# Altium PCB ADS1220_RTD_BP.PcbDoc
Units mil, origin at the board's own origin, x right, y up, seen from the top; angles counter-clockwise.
Board outline 2300 x 1130 mil, 2 copper layers (Top Layer, Bottom Layer), stack 62 mil thick; 26 components, 24 nets, 111 pads, 23 vias.
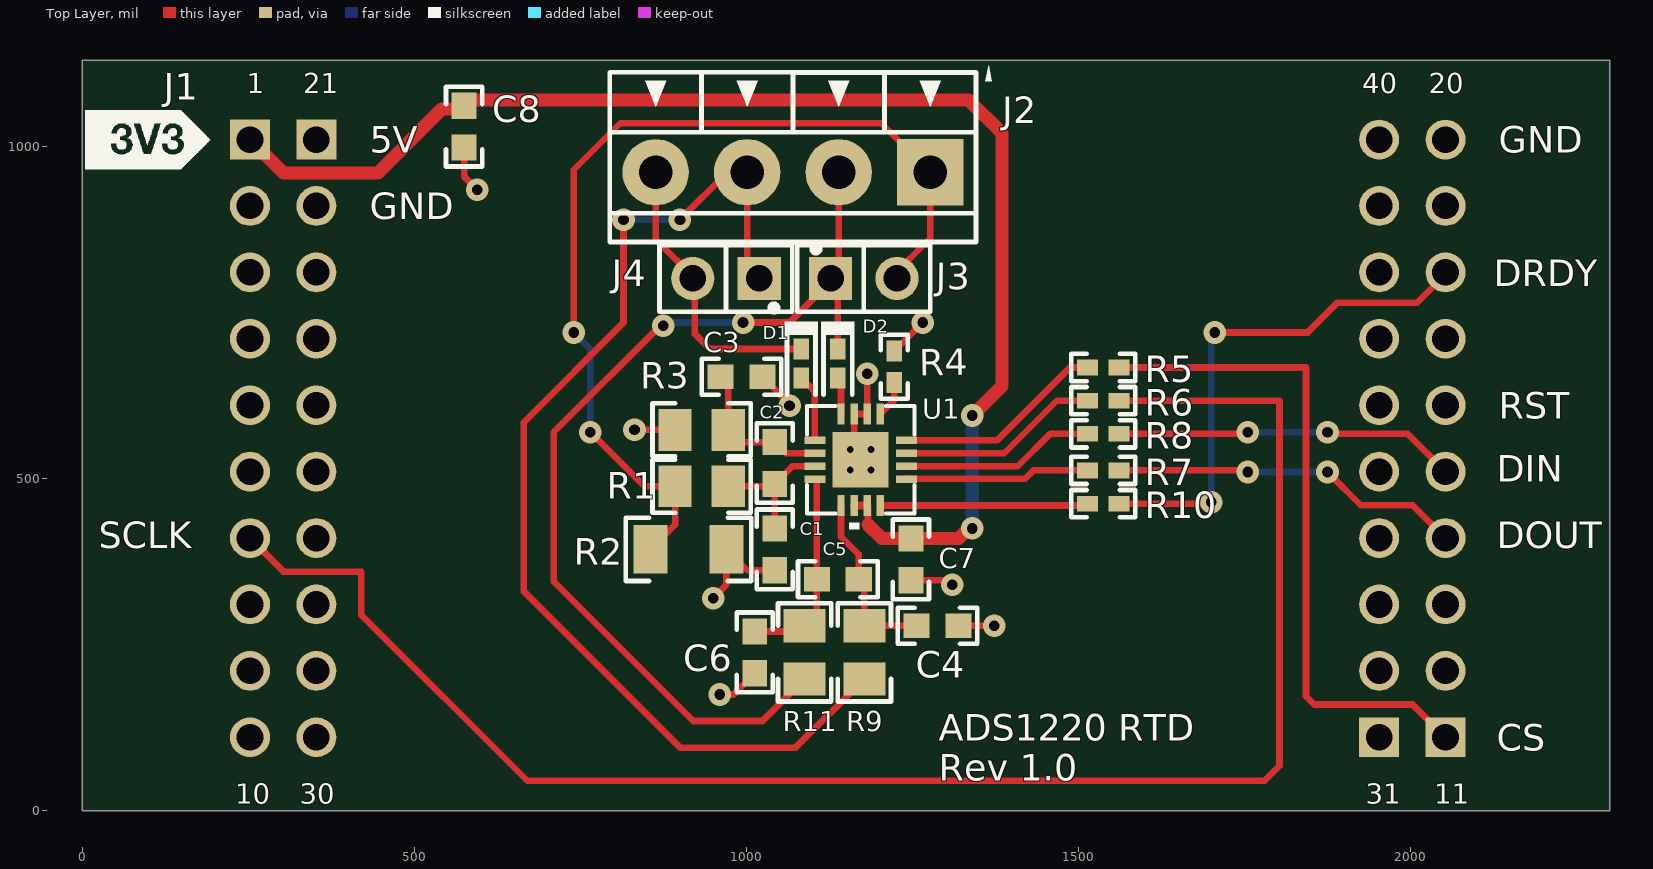
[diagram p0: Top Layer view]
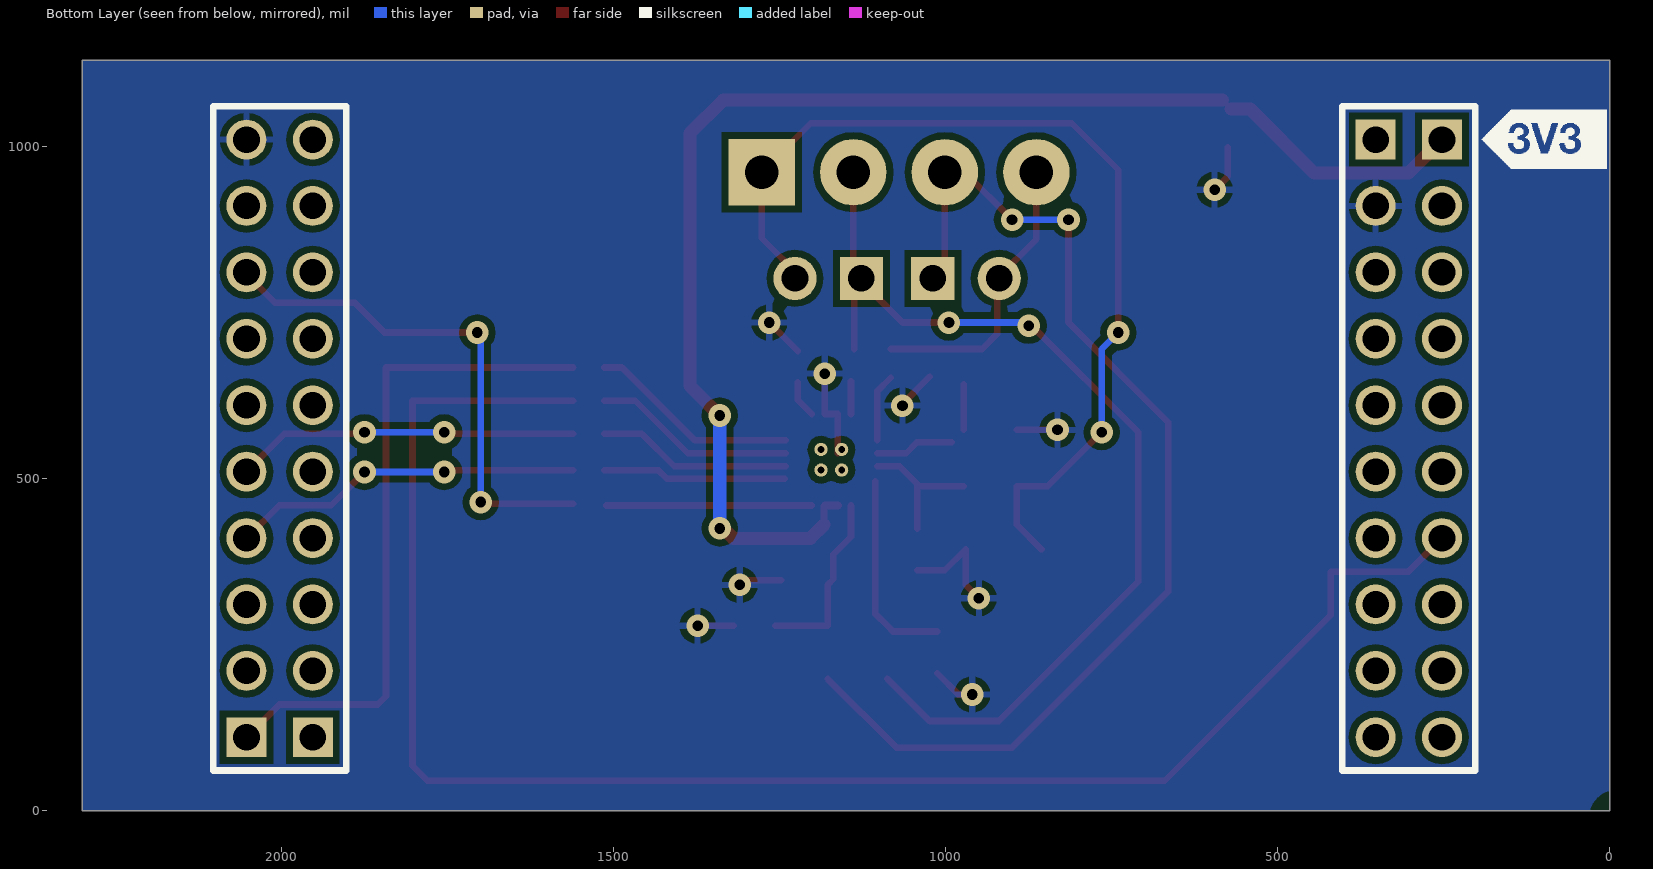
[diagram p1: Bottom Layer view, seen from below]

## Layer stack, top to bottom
Top Solder: solder mask 0.4, Solder Resist, Dk 3.5
Top Layer: signal copper 1.4
Dielectric1: core 59.2, FR-4, Dk 4.8
Bottom Layer: signal copper 1.4
Bottom Solder: solder mask 0.4, Solder Resist, Dk 3.5

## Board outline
0,0 2300,0 2300,1130 0,1130 0,0

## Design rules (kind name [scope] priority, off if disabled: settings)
AcuteAngle [All] p1: minimum=4.50000000000000E+0001 checktracksonly=FALSE
AssemblyTestPointUsage [All] p1: valid=2
Clearance Clearance_BoardEdge_MountingHoles [OnCopper and InComponentClass('Mounting Holes') vs IsKeepOut] p1: gap=40
Clearance Clearance_BoardEdge_Poly [OnCopper and InPoly vs IsKeepOut] p2: gap=25
Clearance Clearance_BoardEdge [OnCopper and Not InComponentClass('Logo') and not InComponentClass('FiducialMark') and not InRegion(1000,500,4000,800) and Not IsKeepout vs IsKeepOut] p3: gap=75
Clearance Clearance_Poly [InPolygon] p4: gap=10
Clearance [All] p5: gap=8
ComponentClearance ComponentClearance_Shunt [InComponentClass('Header') vs InComponentClass('Shunt')] p1: gap=0 collisioncheckmode=3 verticalgap=0 showdistances=FALSE
ComponentClearance ComponentClearance_Logo [InComponentClass('Logo')] p2: gap=0 collisioncheckmode=3 verticalgap=0 showdistances=FALSE
ComponentClearance ComponentClearance_ScrewToNut [(HasFootprint('NY PMS 440 0025 PH')) vs (HasFootprint('Keystone_1902C'))] p3: gap=0 collisioncheckmode=3 verticalgap=0 showdistances=FALSE
ComponentClearance ComponentClearance_MountingHoles [InComponentClass('Mounting Holes')] p4: gap=0 collisioncheckmode=3 verticalgap=100000 showdistances=FALSE
ComponentClearance ComponentClearance_SmallPassives [HasFootprint('0201*') or HasFootprint('0402*') or HasFootprint('0508') or HasFootprint('0603*') or HasFootprint('0612') or HasFootprint('0805*') or HasFootprint('0815*') or HasFootprint('0830*') or HasFootprint('1206*') or HasFootprint('1210*') or HasFootprint('1808*') or HasFootprint('1812*') or HasFootprint('1825*') or HasFootprint('2010*') or HasFootprint('2220*') or HasFootprint('2225*') or HasFootprint('2512*') or HasFootprint('2728*') or HasFootprint('3518*') vs HasFootprint('0201*') or HasFootprint('0402*') or HasFootprint('0508') or HasFootprint('0603*') or HasFootprint('0612') or HasFootprint('0805*') or HasFootprint('0815*') or HasFootprint('0830*') or HasFootprint('1206*') or HasFootprint('1210*') or HasFootprint('1808*') or HasFootprint('1812*') or HasFootprint('1825*') or HasFootprint('2010*') or HasFootprint('2220*') or HasFootprint('2225*') or HasFootprint('2512*') or HasFootprint('2728*') or HasFootprint('3518*')] p5: gap=0 collisioncheckmode=3 verticalgap=0 showdistances=FALSE
ComponentClearance ComponentClearance_THtoSMT [IsThruComponent vs IsSMTComponent] p6: gap=0 collisioncheckmode=3 verticalgap=0 showdistances=FALSE
ComponentClearance ComponentClearance_THtoTH [IsThruComponent vs IsThruComponent] p7: gap=0 collisioncheckmode=3 verticalgap=0 showdistances=FALSE
ComponentClearance [All] p8: gap=0 collisioncheckmode=3 verticalgap=0 showdistances=FALSE
DiffPairsRouting [All] p1: maxlimit=100 minlimit=10 mostfreqgap=10 toplayer_minwidth=15 toplayer_maxwidth=15 toplayer_prefwidth=15 bottomlayer_minwidth=15 bottomlayer_maxwidth=15 bottomlayer_prefwidth=15 maxuncoupledlength=1000
FabricationTestPointUsage TestPointUsage [All] p1: valid=2 allowmultiple=FALSE
FabricationTestpoint Testpoint [All] p1: side=3 testpointundercomponent=TRUE minsize=40 maxsize=100 preferedsize=60 minholesize=0 maxholesize=40 preferedholesize=32 testpointgrid=1 allowsidetop=TRUE allowsidebottom=TRUE usegrid=TRUE gridtolerance=0.01
FanoutControl Fanout_LCC [IsLCC] p1: bgadir=Out bgaviamode=Centered fanoutstyle=Auto fanoutdirection=Alternating viagrid=1 // Fanout_LCC (Default Rule)
FanoutControl Fanout_BGA [IsBGA] p2: bgadir=Out bgaviamode=Centered fanoutstyle=Auto fanoutdirection=Alternating viagrid=1 // Fanout_BGA (Default Rule)
FanoutControl Fanout_Default [All] p4: bgadir=Out bgaviamode=Centered fanoutstyle=Auto fanoutdirection=Alternating viagrid=1 // Fanout_Default (Default Rule)
FanoutControl Fanout_Small [(CompPinCount < 5)] p5: bgadir=Out bgaviamode=Centered fanoutstyle=Auto fanoutdirection=OutThenIn viagrid=1 // Fanout_Small (Default Rule)
HoleSize [All] p1: absolutevalues=TRUE maxlimit=251 minlimit=8 maxpercent=80.000 minpercent=20.000
MinimumAnnularRing MinimumAnnularRing_ThermalPadVias [IsVia and InAnyComponent] p1: minimumring=5.91
MinimumAnnularRing [All] p2: minimumring=9
MinimumSolderMaskSliver MinimumSolderMaskSliver_Logo [InComponentClass('Logo') vs InComponentClass('Logo')] p1: minsoldermaskwidth=0.7
MinimumSolderMaskSliver [All] p2: minsoldermaskwidth=3.94
PlaneConnect [All] p1: planeconnectstyle=Relief reliefexpansion=10 reliefentries=4 reliefconductorwidth=10 reliefairgap=10
PolygonConnect [All] p1: connectstyle=Relief reliefconductorwidth=10 reliefentries=4 polygonreliefangle="90 Angle" airgapwidth=10
RoomDefinition ADS1220_RTD_BP [InComponentClass('ADS1220_RTD_BP')] p1: confinementstyle=ConfineIn formatcopy=TRUE lockcomponents=FALSE outline -692,-1534 1308,-1534 1308,-534 -692,-534
RoutingVias ThermalPadVias [IsVia and InAnyComponent] p1: holewidth=7.87 width=19.68 viastyle="Through Hole" minholewidth=7.87 minwidth=19.68 maxholewidth=12.99 maxwidth=23.62
RoutingVias [All] p2: holewidth=16 width=34 viastyle="Through Hole" minholewidth=7.87 minwidth=26 maxholewidth=40 maxwidth=65
SMDToCorner [All] p1: distance=30000
SilkToSilkClearance [All] p1: silktosilkclearance=5
SilkToSolderMaskClearance SilkscreenOverComponentPads [IsPad] p1: minsilkscreentomaskgap=5 clearancetoexposedcopper=TRUE
SolderMaskExpansion SolderMaskExpansion_via [IsVia] p1: expansion=-17
SolderMaskExpansion [All] p2: expansion=1.97
UnpouredPolygon [All] p1: allowunpoured=FALSE
Width [All] p1: maxlimit=100 minlimit=6 preferedwidth=10 checkconnectedcopper=TRUE
15 further rules are at their usual default settings.

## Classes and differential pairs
component class Header: J3 J4

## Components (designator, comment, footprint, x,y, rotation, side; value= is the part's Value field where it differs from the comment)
C1 "GRM188R72A182KA01D" 0603 1042.65,393.44 r270 top
C2 "C0603C183K1RACTU" 0603 1042.65,523.44 r90 top
C3 "GRM188R72A182KA01D" 0603 992.65,653.44 r180 top
C4 "GRM188R72A272KA01D" 0603 1287.65,278.44 r0 top
C5 "C0603C273K1RACTU" 0603 1137.65,348.44 r180 top
C6 "GRM188R72A272KA01D" 0603 1012.65,238.44 r90 top
C7 "C0603X104K4RACTU" 0603 1247.65,378.44 r270 top
C8 "C0603X104K4RACTU" 0603 575,1030 r270 top
D1 "ZHCS350TA" SOD-523 1082.65,673.44 r270 top
D2 "ZHCS350TA" SOD-523 1137.65,673.44 r270 top
J1 "SSW-110-23-F-D (requires 2)" "40Pin BP" 1152.65,560.53 r0 top
J2 "ED555/4DS" TERM_BLK_ED555-4DS 1276.79,961.38 r180 top
J3 "TSW-102-07-G-S" TSW-102-07-G-S 1176.79,801.38 r0 top
J4 "TSW-102-07-G-S" TSW-102-07-G-S 969.31,801.38 r180 top
R1 "RG2012P-4221-B-T5" 0805_HV 932.65,488.44 r0 top
R2 "PFC-W1206R-12-3241-B" 1206 912.65,393.44 r180 top
R3 "RG2012P-4221-B-T5" 0805_HV 932.65,573.44 r0 top
R4 "CRCW040210K0FKEDHP" 0402 1222.65,668.44 r270 top
R5 "CRCW04020000Z0ED" 0402 1537.39,667.37 r0 top
R6 "CRCW04020000Z0ED" 0402 1537.39,617.37 r0 top
R7 "CRCW04020000Z0ED" 0402 1537.39,512.37 r180 top
R8 "CRCW04020000Z0ED" 0402 1537.39,567.37 r0 top
R9 "RG2012P-4221-B-T5" 0805_HV 1177.65,238.44 r90 top
R10 "CRCW04020000Z0ED" 0402 1537.39,462.37 r180 top
R11 "RG2012P-4221-B-T5" 0805_HV 1087.65,238.44 r90 top
U1 "ADS1220_RVA_16" RVA16_2P14X2P14 1172.09,528.44 r270 top

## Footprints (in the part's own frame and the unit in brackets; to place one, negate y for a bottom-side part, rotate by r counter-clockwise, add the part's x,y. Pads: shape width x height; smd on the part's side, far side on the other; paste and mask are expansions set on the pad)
"40Pin BP" [mil] "40Pin Booster Pack Connection (Top - male; Bottom - female)"
  rect 60x60 hole 40: 1(-900,450) 11(900,-450) 21(-800,450) 31(800,-450)
  round 60 hole 40: 2(-900,350) 3(-900,250) 4(-900,150) 5(-900,50) 6(-900,-50) 7(-900,-150) 8(-900,-250) 9(-900,-350) 10(-900,-450) 12(900,-350) 13(900,-250) 14(900,-150) 15(900,-50) 16(900,50) 17(900,150) 18(900,250) 19(900,350) 20(900,450) 22(-800,350) 23(-800,250) 24(-800,150) 25(-800,50) 26(-800,-50) 27(-800,-150) 28(-800,-250) 29(-800,-350) 30(-800,-450) 32(800,-350) 33(800,-250) 34(800,-150) 35(800,-50) 36(800,50) 37(800,150) 38(800,250) 39(800,350) 40(800,450)
  silkscreen extent -1148,406 -960,494, body extent -950,-500 950,500, height 335
0402 [mm] "0402 from SM-752 data"
  rect 0.8x0.6 smd: 1(-0.6,0) 2(0.6,0)
  silkscreen extent -1.22,-0.52 1.22,0.52, body extent -0.55,-0.3 0.55,0.3, height 0.6
0603 [mm] "0603 from SM-752 data"
  rect 1x0.95 smd: 1(-0.8,0) 2(0.8,0)
  silkscreen extent -1.52,-0.69 1.52,0.69, body extent -0.87,-0.47 0.87,0.47, height 0.85
0805_HV [mil] "0805 with 30mil clearance between pads"
  rect 50x63 smd: 1(-40,0) 2(40,0)
  silkscreen extent -74,-40 74,40, body extent -43,-29 43,29, height 43
1206 [mm] "1206 from SM-752 data"
  rect 1.3x1.85 smd: 1(-1.45,0) 2(1.45,0)
  silkscreen extent -2.4,-1.21 2.4,1.21, body extent -1.7,-0.9 1.7,0.9, height 1.35
RVA16_2P14X2P14 [mm]
  rect 0.8x0.28 smd paste-0.14: 1(-1.75,0.75) 2(-1.75,0.25) 3(-1.75,-0.25) 4(-1.75,-0.75) 9(1.75,-0.75) 10(1.75,-0.25) 11(1.75,0.25) 12(1.75,0.75)
  rect 0.28x0.8 smd paste-0.14: 5(-0.75,-1.75) 6(-0.25,-1.75) 7(0.25,-1.75) 8(0.75,-1.75) 13(0.75,1.75) 14(0.25,1.75) 15(-0.25,1.75) 16(-0.75,1.75)
  rect 2.14x2.14 smd paste-1.057 mask-1.054: 17(0,0)
  round 0.508 / inner round 1.524 / far side round 0.508 hole 0.254: V(-0.394,0.394) V(-0.394,-0.394) V(0.394,0.394) V(0.394,-0.394)
  silkscreen extent -2.06,-2.06 2.66,2.06
SOD-523 [mm] "NXP Semiconductor recommended land pattern, nominal STEP model"
  rect 0.8x0.6 smd paste-0.05: 1(-0.55,0) 2(0.55,0)
  silkscreen extent -1.6,-0.63 1.2,0.64, body extent -0.8,-0.4 0.8,0.4, height 0.72
TERM_BLK_ED555-4DS [mm]
  rect 2.54x2.54 hole 1.27: 1(0,0)
  round 2.54 hole 1.27: 2(3.5,0) 3(7,0) 4(10.5,0)
  silkscreen extent -2.36,-4.09 12.25,2.67, body extent -1.75,-3.8 12.25,2.7, height 8.2
TSW-102-07-G-S [mm] "Samtec 100mil, 1x2, 230 mil above insulator"
  rect 1.65x1.65 hole 1.016 mask+0: 1(-1.27,0)
  round 1.65 hole 1.016 mask+0: 2(1.27,0)
  silkscreen extent -3.56,-1.27 2.54,1.27, body extent -2.54,-1.27 2.54,1.27, height 8.38

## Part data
C1 C3: "CAP, CERM, 1800pF, 100V, +/-10%, X7R, 0603"
C2: "CAP, CERM, 0.018uF, 100V, +/-10%, X7R, 0603"
C4 C6: "CAP, CERM, 2700pF, 100V, +/-10%, X7R, 0603"
C5: "CAP, CERM, 0.027uF, 100V, +/-10%, X7R, 0603"
C7 C8: "CAP, CERM, 0.1uF, 16V, +/-10%, X7R, 0603"
D1 D2: "Diode, Schottky, 40V, 0.35A, SOD-523"
J1: library part "40Pin Booster Pack Connection", "40Pin Booster Pack Connection"
J2: "Terminal Block, 6A, 3.5mm Pitch, 4-Pos, TH"
J3 J4: "Header, 100mil, 2x1, Gold, TH"
R1 R3 R9 R11: "RES, 4.22k ohm, 0.1%, 0.125W, 0805"
R2: "RES, 3.24k ohm, 0.1%, 0.333W, 1206"
R4: library part Resistor, "RES, xxx ohm, x%, xW, [PackageReference]"
R5 R6 R7 R8 R10: "RES, 0 ohm, 5%, 0.063W, 0402"
U1: "Imported"

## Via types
v1: diameter 34, hole 16, Top Layer to Bottom Layer, 23 vias

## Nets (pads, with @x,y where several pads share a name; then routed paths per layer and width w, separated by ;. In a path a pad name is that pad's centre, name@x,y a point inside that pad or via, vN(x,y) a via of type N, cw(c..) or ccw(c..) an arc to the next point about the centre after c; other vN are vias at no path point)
+3V3: C7.1 C8.1 J1.1 U1.10 U1.11 | length 2041.9
  Top Layer w10: U1.11 1183.11,458.37 1183.11,430.79 ; v1(1340,425) v1@1340,430
  Top Layer w12: U1.10 U1.11
  Top Layer w20: J1.1 303.18,960 445,960 541.5,1056.5 C8.1@570,1056.5 ; C8.1@583.5,1070 1295,1070 1335,1070 1385,1020 1385,640 v1(1340,595) ; 1183.11,430.79 1203.96,409.93 C7.1 1319.93,409.93 v1@1340,430
  Bottom Layer w20: v1(1340,425) v1(1340,595)
+5V: J1.21
ADS_CS: J1.11 R5.2 | length 1012.3
  Top Layer w10: R5.2 1842.63,667.37 1842.63,172.37 1855,160 2003.18,160 J1.11
ADS_DRDY: J1.18 R10.1 | length 781.3
  Top Layer w10: R10.1 1697.63,462.37 v1(1700,464.74) ; v1(1705,720) 1845,720 1890,765 2010,765 J1.18@2052.65,807.65
  Bottom Layer w10: v1(1700,464.74) 1700,715 v1(1705,720)
ADS_REFN0: C2.2 C3.2 R3.2 U1.6 | length 187.4
  Top Layer w10: R3.2 C3.2@972.65,641.94 ; R3.2@991.16,554.93 C2.2 1059.3,538.28 U1.6
ADS_REFP0: C1.1 C2.1 R1.2 U1.7 | length 210
  Top Layer w10: R1.2 1039.15,488.44 C2.1 ; C1.1 C2.1 ; U1.7 1069.3,518.59 C2.1
GND: C1.2 C3.1 C4.2 C6.1 C7.2 C8.2 J1.20 J1.22 R2.1 R3.1 R4.1 U1.2 U1.3 U1.17 | length 746.4
  Top Layer w10: C8.2 575,955 v1(595,935) ; v1(831.56,573.44) R3.1 ; v1(950,320) 969.74,339.74 R2.1 1001.24,361.94 C1.2 ; v1(960,175) 980.71,175 C6.1 ; C3.1 1065,612.59 v1(1065,610) ; U1.17@1162.25,538.28 U1.3 U1.2 v1(1181.93,658.07) ; R4.1 v1(1265.59,735) ; C7.2 1303.06,346.94 v1(1310,340) ; C4.2 v1(1373.44,278.44)
NetC4_1: C4.1 C5.1 R9.2 U1.9 | length 274.1
  Top Layer w10: U1.9 1142.56,412.44 1169.15,385.85 C5.1 1177.65,339.93 R9.2 C4.1
NetC5_2: C5.2 C6.2 R11.2 U1.8 | length 303.7
  Top Layer w10: C6.2 1079.15,269.93 R11.2 1106.16,296.94 C5.2 U1.8@1106.16,495.94
NetD1_1: D1.1 J2.4 J4.2 | length 437.8
  Top Layer w10: J2.4 863.4,860.4 922.42,801.38 922.42,717.58 944.91,695.09 D1.1
NetD1_2: D1.2 U1.5 | length 102.3
  Top Layer w10: D1.2 1103.19,631.24 U1.5
NetD2_1: D2.1 J2.2 J3.1 R11.1 | length 1500.3
  Top Layer w10: v1(875,730) 870,730 710,570 710,345 920,135 1024.22,135 R11.1 ; v1(995,735) 1065,735 J3.1@1132.96,802.96 ; D2.1 J3.1@1137.65,801.62 ; J3.1@1138.99,802.96 J2.2
  Bottom Layer w10: v1(875,730) 880,735 v1(995,735)
NetD2_2: D2.2 U1.4 | length 49.5
  Top Layer w10: U1.4 D2.2@1142.56,646.87
NetJ2_1: J2.1 J3.2 R1.1 R2.2 | length 1458.5
  Top Layer w10: v1(740,720) 740,965 810,1035 1203.17,1035 J2.1 1276.79,862.01 J3.2@1216.16,801.38 ; v1(765,570) 846.56,488.44 R1.1 892.65,430.52 R2.2
  Bottom Layer w10: v1(740,720) 765,695 v1(765,570)
NetJ2_3: J2.3 J4.1 R9.1 | length 1650.7
  Top Layer w10: v1(815,890) 815,735 665,585 665,330 900,95 1074.22,95 R9.1 ; v1(900,890) 971.38,961.38 J2.3 J4.1@1001.2,801.42
  Bottom Layer w10: v1(815,890) v1(900,890)
NetR4_2: R4.2 U1.1 | length 56.2
  Top Layer w10: U1.1 1222.65,618.37 R4.2
NetR5_1: R5.1 U1.16 | length 318.1
  Top Layer w10: U1.16 1377.97,557.97 1487.37,667.37 R5.1
NetR6_1: R6.1 U1.15 | length 305.5
  Top Layer w10: U1.15 1388.28,538.28 1467.37,617.37 R6.1
NetR7_2: R7.2 U1.13 | length 276.8
  Top Layer w10: U1.13@1242.09,500 1420,500 1432.37,512.37 R7.2
NetR8_1: R8.1 U1.14 | length 293
  Top Layer w10: U1.14 1408.59,518.59 1457.37,567.37 R8.1
NetR10_2: R10.2 U1.12 | length 309.3
  Top Layer w10: U1.12 R10.2@1510.94,459.54
SPI_CLK: J1.7 R6.2 | length 2540.2
  Top Layer w10: J1.7 303.18,360 420,360 420,295 670,45 1780,45 1802.63,67.63 1802.63,617.37 R6.2
SPI_MISO: J1.14 R7.1 | length 533.8
  Top Layer w10: R7.1 1752.63,512.37 v1(1755,510) ; v1(1875,510) 1925,460 2003.18,460 J1.14
  Bottom Layer w10: v1(1755,510) v1(1875,510)
SPI_MOSI: J1.15 R8.2 | length 517.4
  Top Layer w10: R8.2 1752.63,567.37 v1(1755,569.74) ; v1(1875,570) 1877.47,567.53 1995.65,567.53 J1.15
  Bottom Layer w10: v1(1755,569.74) 1874.74,569.74 v1(1875,570)
pads on no net: J1.2 J1.3 J1.4 J1.5 J1.6 J1.8 J1.9 J1.10 J1.12 J1.13 J1.16 J1.17 J1.19 J1.23 J1.24 J1.25 J1.26 J1.27 J1.28 J1.29 J1.30 J1.31 J1.32 J1.33 J1.34 J1.35 J1.36 J1.37 J1.38 J1.39 J1.40 U1.V

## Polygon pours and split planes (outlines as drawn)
GND on Bottom Layer "BOT_GND" (solid, remove dead copper, pour order 2): 0,0 2300,0 2300,1130 0,1130 0,0

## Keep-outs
Keep-Out Layer:
  text ".Layer_Name" at 577,-858.49 h60

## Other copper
Top Layer:
  text ".Layer_Name" at 577,-858.49 h60
Bottom Layer:
  text ".Layer_Name" at 577,-858.49 h60

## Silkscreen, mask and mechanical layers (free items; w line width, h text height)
Top Overlay:
  text "DRDY" at 2125,790 h40
  text "DIN" at 2130,495 h40
  text "SCLK" at 25,395 h40
  text "DOUT" at 2130,395 h40
  text "ADS1220 RTD" at 1290,105 h40
  text "CS" at 2130,90 h40
  text "Rev 1.0" at 1290,45 h40
  text ".Layer_Name" at 577,-858.49 h60
Bottom Overlay:
  text ".Layer_Name" at 577,-858.49 h60
Top Paste:
  text ".Layer_Name" at 577,-858.49 h60
Bottom Paste:
  text ".Layer_Name" at 577,-858.49 h60
Top Solder:
  text ".Layer_Name" at 577,-858.49 h60
  text ".Layer_Name" at 577,-858.49 h60
Bottom Solder:
  text ".Layer_Name" at 577,-858.49 h60
Drill Guide:
  text ".Layer_Name" at 577,-858.49 h60
M1 Board Outline:
  the board outline again, w10
  text ".Layer_Name" at 577,-858.49 h60
M2 Board Dimensions:
  rectangle: 124.5,-410.5 499.5,-285.5
  rectangle: -0.5,-285.5 124.5,-160.5
  lines w7: -0.5,-285.5 999.5,-285.5 ; 124.5,-410.5 124.5,-160.5 ; 249.5,-410.5 249.5,-160.5 ; 499.5,-410.5 499.5,-160.5 ; 749.5,-410.5 749.5,-160.5 ; -0.5,-410.5 -0.5,-160.5 999.5,-160.5 999.5,-410.5 -0.5,-410.5
  lines w10: -0.5,-475.5 -0.5,-455.5 ; 59.5,-485.5 -0.5,-465.5 ; 59.5,-445.5 -0.5,-465.5 ; 223.58,-465.5 -0.5,-465.5 ; 775.42,-465.5 999.5,-465.5 ; 939.5,-485.5 999.5,-465.5 ; 939.5,-445.5 999.5,-465.5 ; 999.5,-475.5 999.5,-455.5
  text "1000 (mil)" at 233.58,-501.49 h60
  text ".Layer_Name" at 577,-858.49 h60
M3 3D STEP Top:
  text ".Layer_Name" at 577,-858.49 h60
M4 3D STEP Bottom:
  text ".Layer_Name" at 577,-858.49 h60
M5 Assembly Top:
  lines w10: -292,-930.17 6308,-930.17 ; -292,-726.83 6310,-726.83 ; -292,-523.5 -292,-1133.5 3713,-1133.5 6310,-1133.5 6310,-523.5 -291.5,-523.5 -291.5,-1133.5 1284,-1133.5 ; 2173,-1133.5 2173,-523.5 ; 3440,-726.83 3440,-523.5 ; 4280,-726.83 4280,-523.5 ; 4902,-1140 4902,-937.17
  text "COMPONENTS MARKED 'DNP' SHOULD NOT BE POPULATED." at 1153.5,-318.5 h60
  text "ASSEMBLY VARIANT:" at 1153,-434 h60
  text ".VariantName" at 2189,-434 h60
  text "PCB VIEWED FROM TOP SIDE" at -228.5,-655.67 h60
  text "BOARD #:" at 2248,-655.67 h60
  text ".PRJ_Number" at 2793.5,-655.67 h60
  text "REV:" at 3638,-655.67 h60
  text ".PCB_Rev" at 3929.5,-655.67 h60
  text "SVN REV:" at 4476,-655.67 h60
  text ".VersionControl_RevNumber" at 4982,-655.67 h60
  text "IGNORE ->" at -228.5,-858.49 h60
  text "PLOT NAME =" at -228.5,-1064.34 h60
  text ".plot_File_Name" at 577,-1064.34 h60
  text "GENERATED    :" at 2250,-1064.34 h60
  text ".Print_Date" at 3119.5,-1064.34 h60
  text ".Print_Time" at 3848.5,-1064.34 h60
  text "TEXAS INSTRUMENTS" at 5113,-1064.34 h60
M6 Assembly Bottom:
  lines w10: -292.5,-727.33 6309.5,-727.33 ; -290.5,-930.67 6309.5,-930.67 ; 1115.5,-1140.5 1115.5,-937.67 ; 1737.5,-727.33 1737.5,-524 ; 2577.5,-727.33 2577.5,-524 ; 3844.5,-1134 3844.5,-524 ; 4733.5,-1134 6309,-1134 6309,-524 -292.5,-524 -292.5,-1134 2304.5,-1134 6309.5,-1134 6309.5,-524
  text "COMPONENTS MARKED 'DNP' SHOULD NOT BE POPULATED." at 6102,-318 h60
  text ".VariantName" at 5058,-434 h60
  text "ASSEMBLY VARIANT:" at 6097,-434 h60
  text ".VersionControl_RevNumber" at 1035.5,-656.17 h60
  text "SVN REV:" at 1541.5,-656.17 h60
  text ".PCB_Rev" at 2088,-656.17 h60
  text "REV:" at 2379.5,-656.17 h60
  text ".PRJ_Number" at 3224,-656.17 h60
  text "BOARD #:" at 3769.5,-656.17 h60
  text "PCB VIEWED FROM BOTTOM SIDE" at 6246,-656.17 h60
  text "IGNORE ->" at 2547.85,-858.49 h60
  text "TEXAS INSTRUMENTS" at 904.5,-1064.84 h60
  text ".Print_Time" at 2169,-1064.84 h60
  text ".Print_Date" at 2898,-1064.84 h60
  text "GENERATED    :" at 3767.5,-1064.84 h60
  text ".plot_File_Name" at 5440.5,-1064.84 h60
  text "PLOT NAME =" at 6246,-1064.84 h60
M9 Title Sheet:
  drawing of 57 lines, arcs and shapes, not listed
  text "1" at 739.84,8036.5 h70
  text "2" at 3235.5,8036.5 h70
  text "3" at 5724.84,8036.5 h70
  text "4" at 8231.51,8036.5 h70
  text "5" at 10730.5,8036.5 h70
  text "6" at 13235.5,8036.5 h70
  text "A" at -416.5,6893.5 h70
  text "A" at 14383.5,6893.5 h70
  text "B" at -416.5,4513.5 h70
  text "B" at 14383.5,4513.5 h70
  text "C" at -416.5,2138.5 h70
  text "C" at 14383.5,2138.5 h70
  text "PROJECT TITLE:" at 11343.5,277.5 h45
  text ".PRJ_Title" at 11393.5,144.17 h70
  text "DESIGNED FOR:" at 11343.5,-23.5 h45
  text ".PRJ_Customer" at 11393.5,-163.5 h70
  text "D" at -416.5,-231.5 h70
  text "D" at 14383.5,-231.5 h70
  text "FILE NAME:" at 11343.5,-323.5 h45
  text ".PCB_File_Name_No_Path" at 11393.5,-443.5 h70
  text "Texas Instruments (TI) and/or its licensors do not warrant the accuracy or completeness of this specification" at 6374,-605.34 h45
  text "ENGINEER:" at 11343.5,-613.5 h45
  text "LAYOUT BY:" at 12848.5,-613.5 h45
  text "or any information contained therein. TI and/or its licensors do not warrant that this design will meet" at 6329.01,-718 h45
  text ".PRJ_Engineer" at 11393.5,-768.49 h70
  text ".PCB_Layout" at 12899,-768.49 h70
  text "the specifications, will be suitable for your application or fit for any particular purpose, or will operate in" at 6329.01,-830.67 h45
  text ".Layer_Name" at 577,-858.49 h60
  text "ALTIUM DESIGNER VERSION:" at 12848.5,-923.5 h45
  text "an implementation. TI and/or its licensors do not warrant that the design is production worthy. You should" at 6329.01,-943.33 h45
  text "completely validate and test your design implementation to confirm the system functionality for your application." at 6374,-1056 h45
  text ".print_Scale" at 11393.5,-1056.83 h70
  text ".Application_BuildNumber" at 12899,-1056.83 h70
  text "1" at 739.84,-1263.5 h70
  text "2" at 3235.5,-1263.5 h70
  text "3" at 5724.84,-1263.5 h70
  text "4" at 8231.51,-1263.5 h70
  text "5" at 10730.5,-1263.5 h70
  text "6" at 13235.5,-1263.5 h70
M10 Fab Notes:
  drawing of 212 lines, arcs and shapes, not listed
  text "DESIGN INFORMATION" at 12381.02,6810 h60
  text "(REFER ALSO ARRAY/PANEL PROFILING INFORMATION)" at 12019.46,6648.29 h60
  text "BOARD SIZE" at 11333.46,6644 h60
  text "3450MIL" at 11795.78,6516.18 h60
  text "X" at 12301.46,6516.18 h60
  text "4950MIL" at 12532.78,6516.18 h60
  text "Number of Layers :" at 11736.46,6319 h60
  text "2" at 12831.27,6309 h60
  text "MIN. TRACK WIDTH:" at 11736.46,6180 h60
  text "8" at 12832.7,6180 h60
  text "MIL" at 12987.46,6180 h60
  text "MIN. CLEARANCE:" at 11736.46,6048 h60
  text "8" at 12832.7,6048 h60
  text "MIL" at 12987.46,6048 h60
  text "MIN. VIA PAD SIZE:" at 11736.46,5916 h60
  text "24" at 12802.71,5916 h60
  text "MIL" at 12987.46,5916 h60
  text "0.05mm (2MIL)" at 12431.46,5774.29 h60
  text "MINIMUM ANNULAR RING" at 11407.23,5770 h60
  text "EXTERNAL" at 13139.46,5770 h60
  text "PER" at 11607.23,5652 h60
  text "IPC-D-275 CLASS 2 LEVEL C" at 11827.23,5652 h60
  text "MIL, HOLES" at 13315.46,5539.71 h60
  text "+/-" at 12923,5539 h60
  text "+/-" at 13777,5539 h60
  text "REGISTRATION TOLERANCES:" at 11407.23,5534 h60
  text "METAL" at 12607,5534 h60
  text "5" at 13183.2,5534 h60
  text "3" at 14016.2,5534 h60
  text "MIL" at 14132.46,5534 h60
  text "MATERIAL:" at 11332.46,5324.54 h60
  text "FR-4 High Tg" at 12318.9,5184.21 h60
  text "FR-408" at 11753.46,5175.64 h60
  text "X" at 12165.46,5175.64 h60
  text "OTHER" at 13241.46,5175.64 h60
  text "62 MIL (1.6mm) +/-10%" at 12073.56,5012.92 h60
  text "THICKNESS:" at 11407.23,5008.64 h60
  text "X" at 11945.4,5008.64 h60
  text "OTHER" at 13358.46,5008.64 h60
  text "TOLERANCE:" at 11407.23,4850.64 h60
  text "X" at 12246.53,4850.64 h60
  text "ANSI IPC-6012 TYPE 3 CLASS 2" at 12433.48,4850.64 h60
  text "OTHER +/-" at 12433.46,4694.64 h60
  text "BOW & TWIST:" at 11407.23,4537.64 h60
  text "X" at 12246.53,4537.64 h60
  text "ANSI IPC-6012 TYPE 3 CLASS 2" at 12433.48,4537.64 h60
  text "OTHER +/-" at 12433.46,4379.13 h60
  text "COPPER THICKNESS (FINISHED):" at 11332.46,4243.64 h60
  text "1.4MIL (1oz)" at 12212.46,4090.92 h60
  text "2MIL (1.4oz)" at 12979.46,4090.92 h60
  text "2.8MIL (2oz)" at 13706.46,4090.92 h60
  text "OUTER:" at 11689.46,4086.64 h60
  text "X" at 12084,4086 h60
  text "1.4MIL (1oz)" at 12212.46,3933.92 h60
  text "2.8MIL (2oz)" at 12979.46,3933.92 h60
  text "N/A" at 13706,3934.29 h60
  text "INNER SIGNAL:" at 11400.38,3929.64 h60
  text "X" at 12085.42,3929.64 h60
  text "DRILLING:" at 11332.46,3790.64 h60
  text "REFERENCE:" at 11407.23,3673.64 h60
  text "X" at 12055.46,3673.64 h60
  text "AS SHOWN" at 12242.46,3673.64 h60
  text "X" at 12956.46,3673.64 h60
  text "NC_DRILL FILES" at 13093.46,3673.64 h60
  text "PTH MIN COPPER THICKNESS:" at 11407.23,3515.64 h60
  text "X" at 12757.46,3515.64 h60
  text "1MIL" at 12894.46,3515.64 h60
  text "OTHER" at 13391.46,3515.64 h60
  text "BOARD FINISH:" at 11332.46,3356.64 h60
  text "SILKSCREEN:" at 11487.68,3238.64 h60
  text "X" at 12436.46,3238.64 h60
  text "TOP" at 12562.46,3238.64 h60
  text "X" at 12946.46,3238.64 h60
  text "BOTTOM" at 13073.46,3238.64 h60
  text "SILKSCREEN COLOR:" at 11487.68,3071.64 h60
  text "X" at 12435.42,3071.64 h60
  text "WHITE" at 12562.46,3071.64 h60
  text "OTHER" at 13073.46,3071.64 h60
  text "SOLDER RESIST COLOR:" at 11487.68,2901.64 h60
  text "X" at 12055.42,2742.44 h60
  text "GREEN" at 12182.46,2742.44 h60
  text "BLUE" at 12773.46,2742.44 h60
  text "OTHER" at 13311.46,2742.44 h60
  text "IMMERSION GOLD (ENIG)" at 12393.46,2553.92 h60
  text "ENEPIG" at 13731,2550.64 h60
  text "SURFACE FINISH:" at 11332.46,2549.64 h60
  text "X" at 12206.51,2549.64 h60
  text "IMM. TIN/SILVER OR EQUIV" at 11662,2392.64 h60
  text "OTHER" at 13093.46,2392.64 h60
  text "ARRAY/PANEL:" at 11332.46,2213.64 h60
  text "CUT AND TRIM PER MECH LAYER 1" at 12393.46,2209.35 h60
  text "N.C. ROUTE" at 12393.46,2057.64 h60
  text "X" at 13072.46,2057.64 h60
  text "V. SCORE" at 13259.46,2057.64 h60
  text "CERTIFICATION:" at 11332.46,1920.64 h60
  text "MATERIALS AND WORKMANSHIP FOR ALL PCBS" at 12057.46,1920.64 h60
  text "TO MEET OR EXCEED THE REQUIREMENTS OF:" at 12057.46,1822.64 h60
  text "X" at 11683.96,1686.13 h60
  text "ANSI IPC-A-600F CLASS ->" at 11822.96,1686.13 h60
  text "X" at 13462.02,1686.13 h60
  text "2" at 13580.96,1686.14 h60
  text "1" at 13265.96,1684.64 h60
  text "3" at 13934.96,1684.64 h60
  text "X" at 11686.02,1526.64 h60
  text "UL 94V-0" at 11822.96,1526.64 h60
  text "X" at 12498.02,1526.64 h60
  text "RoHS" at 12634.96,1526.64 h60
  text "OTHER" at 13279.36,1526.64 h60
  text "PER ORDER" at 13676.42,1526.64 h60
  text "ADDITIONAL REQUIREMENTS:" at 11332.46,1385.64 h60
  text "MICROSECTION:" at 11407.23,1270.64 h60
  text "YES" at 12312.96,1270.64 h60
  text "REQUIRED" at 13174.46,1114.49 h60
  text "BARE BOARD ELEC. TEST:" at 11407.23,1111.64 h60
  text "NONE" at 12712.96,1111.64 h60
  text "X" at 13047.46,1111.64 h60
  text "PER ORDER" at 13766.46,1111.64 h60
  text "MANUFACTURER'S UL:" at 11407.23,954.64 h60
  text "RAIL" at 12572.96,950.35 h60
  text "METAL" at 13064.77,950.35 h60
  text "X" at 13440,950 h60
  text "SILK" at 13576.46,950.35 h60
  text ".Layer_Name" at 577,-858.49 h60
M11 Gerber Information:
  lines w10: -292,-930.17 6308,-930.17 ; -292,-726.83 6310,-726.83 ; -292,-523.5 -292,-1133.5 3713,-1133.5 6310,-1133.5 6310,-523.5 -291.5,-523.5 -291.5,-1133.5 1284,-1133.5 ; 2173,-1133.5 2173,-523.5 ; 3440,-726.83 3440,-523.5 ; 4280,-726.83 4280,-523.5 ; 4902,-1140 4902,-937.17
  text "ALL ARTWORK VIEWED FROM TOP SIDE" at -228.5,-655.67 h60
  text "BOARD #:" at 2248,-655.67 h60
  text ".PRJ_Number" at 2793.5,-655.67 h60
  text "REV:" at 3638,-655.67 h60
  text ".PCB_Rev" at 3929.5,-655.67 h60
  text "SVN REV:" at 4476,-655.67 h60
  text ".VersionControl_RevNumber" at 4982,-655.67 h60
  text "LAYER NAME =" at -228.5,-858.49 h60
  text "PLOT NAME =" at -228.5,-1064.34 h60
  text ".plot_File_Name" at 577,-1064.34 h60
  text "GENERATED    :" at 2250,-1064.34 h60
  text ".Print_Date" at 3119.5,-1064.34 h60
  text ".Print_Time" at 3848.5,-1064.34 h60
  text "TEXAS INSTRUMENTS" at 5113,-1064.34 h60
M12 Stackup:
  lines w6: 11360,7460 13910,7460 ; 11360,7564.4 13910,7564.4 ; 11300,6975 ccw(c11334,6975) 11334,6941 13936,6941 ccw(c13936,6975) 13970,6975 13970,7681 ccw(c13936,7681) 13936,7715 11334,7715 ccw(c11334,7681) 11300,7681 11300,6975
  text "The Stackup Legend below this is static." at 11605.5,7874.5 h60
  text "If you change the stackup, update the Legend." at 11615.5,7784.5 h60
  text "Layer Stack Up Detail for: Ref_Design.PcbDoc" at 11360,7597.1 h57
  text "Layer" at 11360,7525.4 h24
  text "Gerber" at 12255.81,7525.4 h24
  text "Copper" at 12819.33,7525.4 h24
  text "Dielectric" at 13422.04,7525.4 h24
  text "Name" at 11360,7477.4 h24
  text "Document" at 12255.81,7477.4 h24
  text "Thickness" at 12819.33,7477.4 h24
  text "Material" at 13422.04,7477.4 h24
  text "Top Solder Mask" at 11360,7384.44 h34
  text "(.GTS)" at 12255.81,7384.44 h34
  text "Solder Resist" at 13422.04,7384.44 h34
  text "Top Layer" at 11360,7287.69 h34
  text "(.GTL)" at 12255.81,7287.69 h34
  text "1.4mil" at 12819.33,7287.69 h34
  text "FR-4" at 13422.04,7239.31 h34
  text "Bottom Layer" at 11360,7190.94 h34
  text "(.GBL)" at 12255.81,7190.94 h34
  text "1.4mil" at 12819.33,7190.94 h34
  text "Bottom Solder Mask" at 11360,7094.19 h34
  text "(.GBS)" at 12255.81,7094.19 h34
  text "Solder Resist" at 13422.04,7094.19 h34
  text ".Layer_Name" at 577,-858.49 h60
M13 Component Bodies Top:
  text ".Layer_Name" at 577,-858.49 h60
M14 Component Bodies Bottom:
  text ".Layer_Name" at 577,-858.49 h60
M15 Courtyards Top:
  text ".Layer_Name" at 577,-858.49 h60
M16 Courtyards Bottom:
  text ".Layer_Name" at 577,-858.49 h60
Drill Drawing:
  text ".Layer_Name" at 577,-858.49 h60

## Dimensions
0,0 to 2300,0 on M2 Board Dimensions
0,0 to 0,1130 on M2 Board Dimensions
